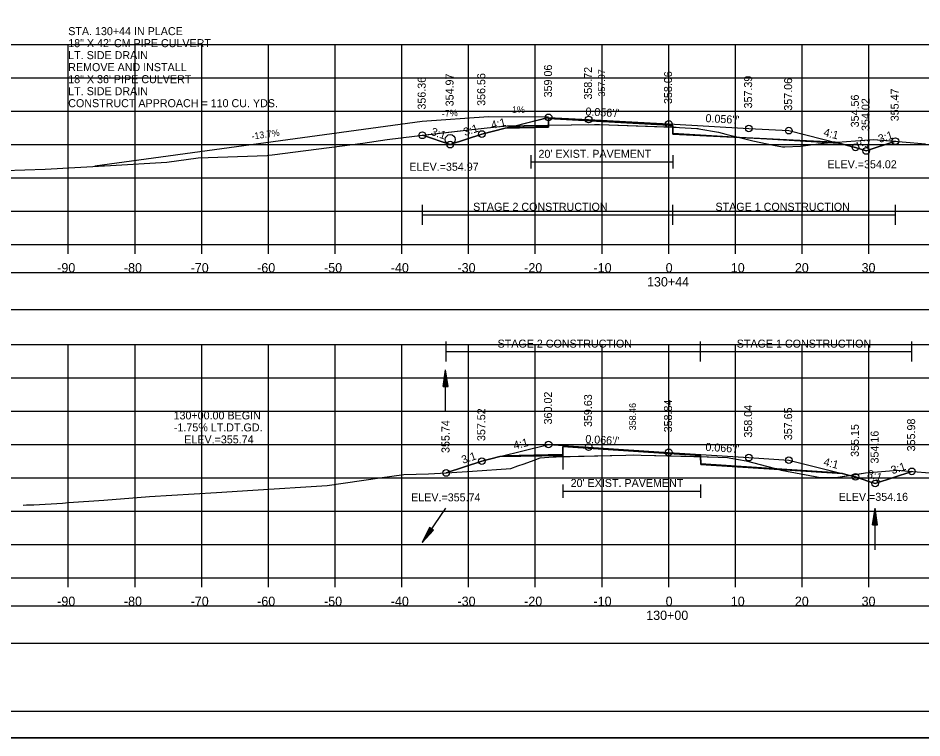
# Model space of a CAD drawing. Extents: x 1376273 to 1384221, y 378927 to 384592.
# Drawn here: x 1376960.2 to 1377095.7, y 381178.5 to 381286.4 of the extents above; entities that cross this region are included whole.
import ezdxf

# ---------------------------------------------------------------- set-up
doc = ezdxf.new("R2010")
doc.units = 0
for name, color, linetype in [('R_Alt Surface', 7, 'Continuous'), ('R_Axis', 7, 'Continuous'), ('R_Axis Annot', 7, 'Continuous'), ('R_Border', 7, 'Continuous'), ('R_Border Notes', 7, 'Continuous'), ('R_Dimension', 7, 'Continuous'), ('R_Drive', 7, 'Continuous'), ('R_Exist Surface', 7, 'Continuous'), ('R_Fin Surface', 7, 'Continuous'), ('R_Grid', 7, 'Continuous'), ('R_No Plot', 7, 'Continuous'), ('R_Water', 7, 'Continuous'), ('R_Xsect Elev', 7, 'Continuous'), ('R_Xsect Slope', 7, 'Continuous'), ('T_Detection Zones', 7, 'Continuous'), ('T_Notes', 7, 'Continuous'), ('T_Vehicle Path Lt Minor', 7, 'Continuous')]:
    doc.layers.add(name, color=color, linetype=linetype)

msp = doc.modelspace()

# ---------------------------------------------------------------- linework, layer by layer
at = {"layer": 'R_Alt Surface'}
for points in [[(1377033.97, 381270.11), (1377039.76, 381270.23), (1377039.77, 381271.4), (1377057.77, 381270.4), (1377058.37, 381270.36), (1377058.38, 381269.2), (1377083.26, 381267.69)], [(1377037.1, 381265.89), (1377037.1, 381263.89)], [(1377058.37, 381265.89), (1377058.37, 381263.89)], [(1377037.1, 381264.89), (1377058.37, 381264.89)], [(1377033.16, 381220.88), (1377041.91, 381221.06), (1377041.92, 381222.22), (1377057.77, 381221.18), (1377062.55, 381220.86), (1377062.56, 381219.69), (1377083.08, 381218.33)], [(1377041.92, 381216.54), (1377041.92, 381214.54)], [(1377041.92, 381215.54), (1377062.55, 381215.54)], [(1377062.55, 381216.54), (1377062.55, 381214.54)]]:
    msp.add_lwpolyline(points, dxfattribs=at)
at = {"layer": 'R_Axis'}
for p, q in [((1376907.77, 381252.51), (1377207.77, 381252.51)), ((1376967.77, 381251.11), (1376967.77, 381252.51)), ((1376977.77, 381251.11), (1376977.77, 381252.51)), ((1376987.77, 381251.11), (1376987.77, 381252.51)), ((1376997.77, 381251.11), (1376997.77, 381252.51)), ((1377007.77, 381251.11), (1377007.77, 381252.51)), ((1377017.77, 381251.11), (1377017.77, 381252.51)), ((1377027.77, 381251.11), (1377027.77, 381252.51)), ((1377037.77, 381251.11), (1377037.77, 381252.51)), ((1377047.77, 381251.11), (1377047.77, 381252.51)), ((1377057.77, 381251.11), (1377057.77, 381252.51)), ((1377067.77, 381251.11), (1377067.77, 381252.51)), ((1377077.77, 381251.11), (1377077.77, 381252.51)), ((1377087.77, 381251.11), (1377087.77, 381252.51)), ((1376907.77, 381202.51), (1377207.77, 381202.51)), ((1376967.77, 381201.11), (1376967.77, 381202.51)), ((1376977.77, 381201.11), (1376977.77, 381202.51)), ((1376987.77, 381201.11), (1376987.77, 381202.51)), ((1376997.77, 381201.11), (1376997.77, 381202.51)), ((1377007.77, 381201.11), (1377007.77, 381202.51)), ((1377017.77, 381201.11), (1377017.77, 381202.51)), ((1377027.77, 381201.11), (1377027.77, 381202.51)), ((1377037.77, 381201.11), (1377037.77, 381202.51)), ((1377047.77, 381201.11), (1377047.77, 381202.51)), ((1377057.77, 381201.11), (1377057.77, 381202.51)), ((1377067.77, 381201.11), (1377067.77, 381202.51)), ((1377077.77, 381201.11), (1377077.77, 381202.51)), ((1377087.77, 381201.11), (1377087.77, 381202.51))]:
    msp.add_line(p, q, dxfattribs=at)
at = {"layer": 'R_Axis Annot'}
for points in [[(1376907.2, 381242.74), (1377209.01, 381242.74), (1377209.01, 381248.26), (1376907.2, 381248.26)], [(1376907.2, 381192.74), (1377209.01, 381192.74), (1377209.01, 381198.26), (1376907.2, 381198.26)]]:
    msp.add_lwpolyline(points, close=True, dxfattribs=at)
at = {"layer": 'R_Border'}
msp.add_line((1377215.95, 381182.51), (1376899.77, 381182.51), dxfattribs=at)
at = {"layer": 'R_Dimension'}
for p, q in [((1377020.84, 381255.46), (1377020.84, 381258.46)), ((1377058.37, 381255.46), (1377058.37, 381258.46)), ((1377091.74, 381255.46), (1377091.74, 381258.46)), ((1377020.84, 381256.96), (1377091.74, 381256.96)), ((1377024.41, 381234.94), (1377024.41, 381237.94)), ((1377062.55, 381234.94), (1377062.55, 381237.94)), ((1377094.21, 381234.94), (1377094.21, 381237.94)), ((1377024.41, 381236.44), (1377094.21, 381236.44))]:
    msp.add_line(p, q, dxfattribs=at)
at = {"layer": 'R_Drive'}
for p, q in [((1377020.79, 381270.95), (1376971.77, 381264.23)), ((1377030.77, 381271.65), (1377020.79, 381270.95)), ((1377039.77, 381271.57), (1377030.77, 381271.65))]:
    msp.add_line(p, q, dxfattribs=at)
at = {"layer": 'R_Exist Surface'}
for points in [[(1376958.21, 381263.6), (1376964.31, 381263.82), (1376974.12, 381264.35), (1376982.56, 381264.83), (1376987.26, 381265.49), (1376997.57, 381265.86), (1376997.82, 381265.88), (1376998.31, 381265.95), (1377011.94, 381267.7), (1377015.58, 381268.25), (1377019.67, 381268.74), (1377028.25, 381269.75), (1377031.49, 381270.08), (1377033.56, 381270.28), (1377033.75, 381270.28), (1377035.49, 381270.31), (1377036.1, 381270.32), (1377046.66, 381270.47), (1377047.4, 381270.48), (1377058.88, 381270.07), (1377059.37, 381270.05), (1377061.96, 381269.88), (1377062.11, 381269.87), (1377062.29, 381269.84), (1377065.23, 381269.34), (1377066.33, 381269.06), (1377070.39, 381268.03), (1377073.47, 381267.42), (1377074.84, 381267.15), (1377075.19, 381267.16), (1377077.51, 381267.24), (1377080.57, 381267.63), (1377082.07, 381267.81), (1377083.05, 381267.87), (1377088.46, 381268.26), (1377093.94, 381267.79), (1377096.25, 381267.59)], [(1376960.99, 381213.43), (1376961.51, 381213.46), (1376962.61, 381213.45), (1376966.88, 381213.73), (1376967.82, 381213.82), (1376973.1, 381214.18), (1376979.95, 381214.72), (1376989.99, 381215.34), (1376995.45, 381215.65), (1377006.57, 381216.37), (1377014.48, 381217.51), (1377018.09, 381218.01), (1377021.76, 381218.13), (1377024.48, 381218.25), (1377028.35, 381218.54), (1377034.1, 381218.93), (1377035.13, 381219.3), (1377036.12, 381219.64), (1377037.62, 381220.18), (1377038.5, 381220.53), (1377040.47, 381220.66), (1377040.92, 381220.69), (1377051.36, 381220.94), (1377052.55, 381220.97), (1377053.65, 381220.93), (1377063.55, 381220.67), (1377063.72, 381220.66), (1377066.58, 381220.58), (1377067.06, 381220.49), (1377069.38, 381220.07), (1377073.56, 381218.96), (1377074.61, 381218.68), (1377079.71, 381217.72), (1377080.47, 381217.57), (1377082.71, 381217.56), (1377082.74, 381217.56), (1377082.84, 381217.57), (1377087.28, 381218.26), (1377087.89, 381218.32), (1377092.08, 381218.66), (1377094.34, 381218.48), (1377099.46, 381218.06)]]:
    msp.add_lwpolyline(points, dxfattribs=at)
at = {"layer": 'R_Fin Surface'}
for points in [[(1377020.84, 381268.87), (1377025.02, 381267.48), (1377029.77, 381269.06), (1377033.26, 381269.94), (1377039.77, 381271.56), (1377045.77, 381271.23), (1377057.77, 381270.57), (1377069.77, 381269.9), (1377075.77, 381269.57), (1377085.77, 381267.07), (1377087.38, 381266.53), (1377091.74, 381267.98)], [(1377024.41, 381218.25), (1377024.42, 381218.25), (1377029.77, 381220.03), (1377032.45, 381220.7), (1377039.77, 381222.53), (1377045.77, 381222.14), (1377057.77, 381221.34), (1377069.77, 381220.55), (1377075.77, 381220.16), (1377085.77, 381217.66), (1377087.75, 381216.99), (1377088.73, 381216.67), (1377094.21, 381218.49)]]:
    msp.add_lwpolyline(points, dxfattribs=at)
at = {"layer": 'R_Grid'}
for p, q in [((1376907.77, 381282.51), (1377207.77, 381282.51)), ((1376907.77, 381282.51), (1377207.77, 381282.51)), ((1376967.77, 381252.51), (1376967.77, 381282.51)), ((1376967.77, 381252.51), (1376967.77, 381282.51)), ((1376977.77, 381252.51), (1376977.77, 381282.51)), ((1376977.77, 381252.51), (1376977.77, 381282.51)), ((1376987.77, 381252.51), (1376987.77, 381282.51)), ((1376987.77, 381252.51), (1376987.77, 381282.51)), ((1376997.77, 381252.51), (1376997.77, 381282.51)), ((1376997.77, 381252.51), (1376997.77, 381282.51)), ((1377007.77, 381252.51), (1377007.77, 381282.51)), ((1377007.77, 381252.51), (1377007.77, 381282.51)), ((1377017.77, 381252.51), (1377017.77, 381282.51)), ((1377017.77, 381252.51), (1377017.77, 381282.51)), ((1377027.77, 381252.51), (1377027.77, 381282.51)), ((1377027.77, 381252.51), (1377027.77, 381282.51)), ((1377037.77, 381252.51), (1377037.77, 381282.51)), ((1377037.77, 381252.51), (1377037.77, 381282.51)), ((1377047.77, 381252.51), (1377047.77, 381282.51)), ((1377047.77, 381252.51), (1377047.77, 381282.51)), ((1377057.77, 381252.51), (1377057.77, 381282.51)), ((1377057.77, 381252.51), (1377057.77, 381282.51)), ((1377067.77, 381252.51), (1377067.77, 381282.51)), ((1377067.77, 381252.51), (1377067.77, 381282.51)), ((1377077.77, 381252.51), (1377077.77, 381282.51)), ((1377077.77, 381252.51), (1377077.77, 381282.51)), ((1377087.77, 381252.51), (1377087.77, 381282.51)), ((1377087.77, 381252.51), (1377087.77, 381282.51)), ((1376907.77, 381277.51), (1377207.77, 381277.51)), ((1376907.77, 381277.51), (1377207.77, 381277.51)), ((1376907.77, 381272.51), (1377207.77, 381272.51)), ((1376907.77, 381272.51), (1377207.77, 381272.51)), ((1376907.77, 381267.51), (1377207.77, 381267.51)), ((1376907.77, 381267.51), (1377207.77, 381267.51)), ((1376907.77, 381262.51), (1377207.77, 381262.51)), ((1376907.77, 381262.51), (1377207.77, 381262.51)), ((1376907.77, 381257.51), (1377207.77, 381257.51)), ((1376907.77, 381257.51), (1377207.77, 381257.51)), ((1376907.77, 381252.51), (1377207.77, 381252.51)), ((1376907.77, 381252.51), (1377207.77, 381252.51)), ((1376907.77, 381237.51), (1377207.77, 381237.51)), ((1376907.77, 381237.51), (1377207.77, 381237.51)), ((1376967.77, 381202.51), (1376967.77, 381237.51)), ((1376967.77, 381202.51), (1376967.77, 381237.51)), ((1376977.77, 381202.51), (1376977.77, 381237.51)), ((1376977.77, 381202.51), (1376977.77, 381237.51)), ((1376987.77, 381202.51), (1376987.77, 381237.51)), ((1376987.77, 381202.51), (1376987.77, 381237.51)), ((1376997.77, 381202.51), (1376997.77, 381237.51)), ((1376997.77, 381202.51), (1376997.77, 381237.51)), ((1377007.77, 381202.51), (1377007.77, 381237.51)), ((1377007.77, 381202.51), (1377007.77, 381237.51)), ((1377017.77, 381202.51), (1377017.77, 381237.51)), ((1377017.77, 381202.51), (1377017.77, 381237.51)), ((1377027.77, 381202.51), (1377027.77, 381237.51)), ((1377027.77, 381202.51), (1377027.77, 381237.51)), ((1377037.77, 381202.51), (1377037.77, 381237.51)), ((1377037.77, 381202.51), (1377037.77, 381237.51)), ((1377047.77, 381202.51), (1377047.77, 381237.51)), ((1377047.77, 381202.51), (1377047.77, 381237.51)), ((1377057.77, 381202.51), (1377057.77, 381237.51)), ((1377057.77, 381202.51), (1377057.77, 381237.51)), ((1377067.77, 381202.51), (1377067.77, 381237.51)), ((1377067.77, 381202.51), (1377067.77, 381237.51)), ((1377077.77, 381202.51), (1377077.77, 381237.51)), ((1377077.77, 381202.51), (1377077.77, 381237.51)), ((1377087.77, 381202.51), (1377087.77, 381237.51)), ((1377087.77, 381202.51), (1377087.77, 381237.51)), ((1376907.77, 381232.51), (1377207.77, 381232.51)), ((1376907.77, 381232.51), (1377207.77, 381232.51)), ((1376907.77, 381227.51), (1377207.77, 381227.51)), ((1376907.77, 381227.51), (1377207.77, 381227.51)), ((1376907.77, 381222.51), (1377207.77, 381222.51)), ((1376907.77, 381222.51), (1377207.77, 381222.51)), ((1376907.77, 381217.51), (1377207.77, 381217.51)), ((1376907.77, 381217.51), (1377207.77, 381217.51)), ((1376907.77, 381212.51), (1377207.77, 381212.51)), ((1376907.77, 381212.51), (1377207.77, 381212.51)), ((1376907.77, 381207.51), (1377207.77, 381207.51)), ((1376907.77, 381207.51), (1377207.77, 381207.51)), ((1376907.77, 381202.51), (1377207.77, 381202.51)), ((1376907.77, 381202.51), (1377207.77, 381202.51))]:
    msp.add_line(p, q, dxfattribs=at)
at = {"layer": 'R_No Plot'}
msp.add_line((1376887.37, 381178.53), (1377220.7, 381178.53), dxfattribs=at)
for points in [[(1376887.36, 381391.86), (1377220.7, 381391.86), (1377220.7, 381178.53), (1376887.36, 381178.53)], [(1377133.69, 381387.97), (1377133.69, 381378.09), (1377169.42, 381378.09), (1377169.42, 381375.17), (1377192.62, 381375.17), (1377192.62, 381350.84), (1377215.95, 381350.84), (1377215.95, 381182.51), (1376899.77, 381182.51), (1376899.77, 381387.97)]]:
    msp.add_lwpolyline(points, close=True, dxfattribs=at)
for points in [[(1377033.26, 381269.94), (1377039.76, 381270.07), (1377039.77, 381271.4), (1377057.77, 381270.4), (1377058.37, 381270.36), (1377058.38, 381269.03), (1377082.72, 381267.83)], [(1377032.45, 381220.7), (1377041.91, 381220.89), (1377041.92, 381222.22), (1377057.77, 381221.18), (1377062.55, 381220.86), (1377062.56, 381219.53), (1377083.81, 381218.15)]]:
    msp.add_lwpolyline(points, dxfattribs=at)
for centre in [(1377039.77, 381271.56), (1377039.77, 381271.56), (1377045.77, 381271.23), (1377045.77, 381271.23), (1377057.77, 381270.57), (1377057.77, 381270.57), (1377029.77, 381269.06), (1377029.77, 381269.06), (1377069.77, 381269.9), (1377069.77, 381269.9), (1377075.77, 381269.57), (1377075.77, 381269.57), (1377020.84, 381268.87), (1377020.84, 381268.87), (1377091.74, 381267.98), (1377091.74, 381267.98), (1377025.02, 381267.48), (1377025.02, 381267.48), (1377025.02, 381267.48), (1377025.02, 381267.48), (1377085.77, 381267.07), (1377085.77, 381267.07), (1377087.38, 381266.53), (1377087.38, 381266.53), (1377087.38, 381266.53), (1377087.38, 381266.53), (1377039.77, 381222.53), (1377039.77, 381222.53), (1377045.77, 381222.14), (1377045.77, 381222.14), (1377057.77, 381221.34), (1377057.77, 381221.34), (1377069.77, 381220.55), (1377069.77, 381220.55), (1377029.77, 381220.03), (1377029.77, 381220.03), (1377075.77, 381220.16), (1377075.77, 381220.16), (1377024.41, 381218.25), (1377024.41, 381218.25), (1377024.42, 381218.25), (1377024.42, 381218.25), (1377024.42, 381218.25), (1377024.42, 381218.25), (1377085.77, 381217.66), (1377085.77, 381217.66), (1377094.21, 381218.49), (1377094.21, 381218.49), (1377088.73, 381216.67), (1377088.73, 381216.67), (1377088.73, 381216.67), (1377088.73, 381216.67)]:
    msp.add_circle(centre, 0.5, dxfattribs=at)
at = {"layer": 'R_Water'}
for p, q in [((1377023.94, 381231.21), (1377024.32, 381233.71)), ((1377024, 381231.21), (1377024.32, 381233.29)), ((1377024.32, 381227.46), (1377024.32, 381233.71)), ((1377024.69, 381231.21), (1377024.32, 381233.71)), ((1377024.63, 381231.21), (1377024.32, 381233.29)), ((1377024.07, 381231.21), (1377024.32, 381232.86)), ((1377024.13, 381231.21), (1377024.32, 381232.45)), ((1377024.2, 381231.21), (1377024.32, 381232.02)), ((1377024.57, 381231.21), (1377024.32, 381232.86)), ((1377024.5, 381231.21), (1377024.32, 381232.45)), ((1377024.44, 381231.21), (1377024.32, 381232.02)), ((1377023.94, 381231.21), (1377024.69, 381231.21)), ((1377024.26, 381231.21), (1377024.32, 381231.61)), ((1377024.38, 381231.21), (1377024.32, 381231.61)), ((1377024.32, 381212.97), (1377020.81, 381207.8)), ((1377088.34, 381210.47), (1377088.72, 381212.97)), ((1377088.72, 381206.72), (1377088.72, 381212.97)), ((1377089.09, 381210.47), (1377088.72, 381212.97)), ((1377088.4, 381210.47), (1377088.72, 381212.55)), ((1377088.47, 381210.47), (1377088.72, 381212.12)), ((1377088.53, 381210.47), (1377088.72, 381211.71)), ((1377089.03, 381210.47), (1377088.72, 381212.55)), ((1377088.96, 381210.47), (1377088.72, 381212.12)), ((1377088.9, 381210.47), (1377088.72, 381211.71)), ((1377021.9, 381210.08), (1377020.81, 381207.8)), ((1377021.96, 381210.04), (1377021.05, 381208.14)), ((1377022.01, 381210.01), (1377021.29, 381208.5)), ((1377022.06, 381209.97), (1377021.52, 381208.84)), ((1377022.52, 381209.66), (1377021.9, 381210.08)), ((1377088.34, 381210.47), (1377089.09, 381210.47)), ((1377088.59, 381210.47), (1377088.72, 381211.28)), ((1377088.66, 381210.47), (1377088.72, 381210.87)), ((1377088.84, 381210.47), (1377088.72, 381211.28)), ((1377088.77, 381210.47), (1377088.72, 381210.87)), ((1377022.52, 381209.66), (1377020.81, 381207.8)), ((1377022.47, 381209.69), (1377021.05, 381208.14)), ((1377022.42, 381209.73), (1377021.29, 381208.5)), ((1377022.37, 381209.76), (1377021.52, 381208.84)), ((1377022.11, 381209.94), (1377021.76, 381209.19)), ((1377022.31, 381209.8), (1377021.76, 381209.19)), ((1377022.17, 381209.9), (1377021.99, 381209.54)), ((1377022.26, 381209.83), (1377021.99, 381209.54))]:
    msp.add_line(p, q, dxfattribs=at)
msp.add_circle((1377025.02, 381268.23), 0.75, dxfattribs=at)
at = {"layer": 'T_Detection Zones'}
for p, q in [((1377041.91, 381220.89), (1377032.45, 381220.7)), ((1377041.91, 381220.89), (1377041.91, 381218.79)), ((1377041.91, 381220.71), (1377041.91, 381220.89))]:
    msp.add_line(p, q, dxfattribs=at)
for points in [[(1377020.84, 381268.87), (1377028.25, 381269.75), (1377031.49, 381270.08), (1377033.56, 381270.28), (1377033.75, 381270.28), (1377035.49, 381270.31), (1377036.1, 381270.32), (1377039.76, 381270.37), (1377039.76, 381270.07), (1377033.26, 381269.94), (1377029.77, 381269.06), (1377025.02, 381267.48)], [(1377058.37, 381270.08), (1377058.88, 381270.07), (1377059.37, 381270.05), (1377061.96, 381269.88), (1377062.11, 381269.87), (1377062.29, 381269.84), (1377065.23, 381269.34), (1377066.33, 381269.06), (1377068.4, 381268.54), (1377058.38, 381269.03)], [(1377068.4, 381268.54), (1377070.39, 381268.03), (1377073.47, 381267.42), (1377074.84, 381267.15), (1377075.19, 381267.16), (1377077.51, 381267.24), (1377080.57, 381267.63), (1377082.07, 381267.81), (1377082.49, 381267.84)], [(1377082.49, 381267.84), (1377083.05, 381267.87), (1377088.46, 381268.26), (1377091.74, 381267.98), (1377087.38, 381266.53), (1377085.77, 381267.07), (1377082.72, 381267.83)], [(1377062.55, 381220.7), (1377063.55, 381220.67), (1377063.72, 381220.66), (1377066.58, 381220.58), (1377067.06, 381220.49), (1377069.38, 381220.07), (1377073.56, 381218.96), (1377074.3, 381218.77), (1377062.56, 381219.53)], [(1377074.3, 381218.77), (1377074.61, 381218.68), (1377079.71, 381217.72), (1377080.47, 381217.57), (1377082.71, 381217.56), (1377082.74, 381217.56), (1377082.84, 381217.57), (1377084.86, 381217.88), (1377083.81, 381218.15)], [(1377084.86, 381217.88), (1377087.28, 381218.26), (1377087.89, 381218.32), (1377092.08, 381218.66), (1377094.21, 381218.49), (1377088.73, 381216.67), (1377087.75, 381216.99), (1377085.77, 381217.66)]]:
    msp.add_lwpolyline(points, close=True, dxfattribs=at)
for points in [[(1377024.41, 381218.25), (1377024.48, 381218.25), (1377028.35, 381218.54), (1377034.1, 381218.93), (1377035.13, 381219.3), (1377036.12, 381219.64), (1377037.62, 381220.18), (1377038.5, 381220.53), (1377040.47, 381220.66), (1377040.92, 381220.69), (1377041.91, 381220.71)], [(1377032.45, 381220.7), (1377029.77, 381220.03), (1377024.41, 381218.25)]]:
    msp.add_lwpolyline(points, dxfattribs=at)
at = {"layer": 'T_Notes'}
for p, q in [((1377020.79, 381270.95), (1376971.77, 381264.23)), ((1377030.77, 381271.65), (1377020.79, 381270.95)), ((1377039.77, 381271.57), (1377030.77, 381271.65))]:
    msp.add_line(p, q, dxfattribs=at)
for points in [[(1377020.84, 381268.87), (1377025.02, 381267.48), (1377029.77, 381269.06), (1377034, 381270.12), (1377034.7, 381270.3), (1377039.77, 381271.57)], [(1376971.77, 381264.23), (1376974.12, 381264.35), (1376982.56, 381264.83), (1376987.26, 381265.49), (1376997.57, 381265.86), (1376997.82, 381265.88), (1376998.31, 381265.95), (1377011.94, 381267.7), (1377015.58, 381268.25), (1377019.67, 381268.74), (1377020.84, 381268.87)]]:
    msp.add_lwpolyline(points, dxfattribs=at)
at = {"layer": 'T_Vehicle Path Lt Minor'}
for p, q in [((1377041.91, 381220.89), (1377041.91, 381220.71)), ((1377062.55, 381220.7), (1377062.55, 381220.86))]:
    msp.add_line(p, q, dxfattribs=at)
msp.add_lwpolyline([(1377039.76, 381270.37), (1377046.66, 381270.47), (1377047.4, 381270.48), (1377058.37, 381270.08), (1377058.37, 381270.36), (1377057.77, 381270.4), (1377039.77, 381271.4)], close=True, dxfattribs=at)
for points in [[(1377062.55, 381220.86), (1377057.77, 381221.18), (1377041.92, 381222.22), (1377041.91, 381220.89)], [(1377041.91, 381220.71), (1377051.36, 381220.94), (1377052.55, 381220.97), (1377053.65, 381220.93), (1377062.55, 381220.7)]]:
    msp.add_lwpolyline(points, dxfattribs=at)

# ---------------------------------------------------------------- texts
at = {"layer": 'R_Alt Surface'}
for p in [(1377038.25, 381265.5), (1377043.07, 381216.15)]:
    msp.add_text("20' EXIST. PAVEMENT", height=1.2, dxfattribs=at).set_placement(p)
at = {"layer": 'R_Axis Annot'}
for s, p in [('-90', (1376966.11, 381248.31)), ('-80', (1376976.11, 381248.31)), ('-70', (1376986.11, 381248.31)), ('-60', (1376996.08, 381248.31)), ('-50', (1377006.11, 381248.31)), ('-40', (1377016.11, 381248.31)), ('-30', (1377026.11, 381248.31)), ('-20', (1377036.11, 381248.31)), ('-10', (1377046.5, 381248.31)), ('0', (1377057.31, 381248.31)), ('10', (1377067.08, 381248.31)), ('20', (1377076.68, 381248.31)), ('30', (1377086.68, 381248.31)), ('130+44', (1377054.52, 381246.21)), ('-90', (1376966.11, 381198.31)), ('-80', (1376976.11, 381198.31)), ('-70', (1376986.11, 381198.31)), ('-60', (1376996.08, 381198.31)), ('-50', (1377006.11, 381198.31)), ('-40', (1377016.11, 381198.31)), ('-30', (1377026.11, 381198.31)), ('-20', (1377036.11, 381198.31)), ('-10', (1377046.5, 381198.31)), ('0', (1377057.31, 381198.31)), ('10', (1377067.08, 381198.31)), ('20', (1377076.68, 381198.31)), ('30', (1377086.68, 381198.31)), ('130+00', (1377054.4, 381196.21))]:
    msp.add_text(s, height=1.4, dxfattribs=at).set_placement(p)
at = {"layer": 'R_Border Notes'}
for s, p in [('ELEV.=354.97', (1377018.89, 381263.56)), ('ELEV.=354.02', (1377081.56, 381263.93)), ('ELEV.=355.74', (1377019.16, 381213.99)), ('ELEV.=354.16', (1377083.25, 381214.07))]:
    msp.add_text(s, height=1.2, dxfattribs=at).set_placement(p)
at = {"layer": 'R_Dimension'}
for s, p in [('STAGE 2 CONSTRUCTION', (1377028.46, 381257.56)), ('STAGE 1 CONSTRUCTION', (1377064.78, 381257.56)), ('STAGE 2 CONSTRUCTION', (1377032.12, 381237.04)), ('STAGE 1 CONSTRUCTION', (1377067.97, 381237.04))]:
    msp.add_text(s, height=1.2, dxfattribs=at).set_placement(p)
at = {"layer": 'R_Drive'}
for s, p in [('STA. 130+44 IN PLACE', (1376967.76, 381283.89)), ('18" X 42\' CM PIPE CULVERT', (1376967.76, 381282.09)), ('LT. SIDE DRAIN', (1376967.76, 381280.29)), ('REMOVE AND INSTALL', (1376967.76, 381278.49)), ('18" X 36\' PIPE CULVERT', (1376967.76, 381276.69)), ('LT. SIDE DRAIN', (1376967.76, 381274.89)), ('CONSTRUCT APPROACH = 110 CU. YDS.', (1376967.76, 381273.09))]:
    msp.add_text(s, height=1.2, dxfattribs=at).set_placement(p)
for s, rotation, p in [('-7%', 4.0253, (1377023.79, 381271.6)), ('1%', 359.4513, (1377034.27, 381272.23)), ('-13.7%', 7.8114, (1376995.3, 381268.23))]:
    msp.add_text(s, height=1, rotation=rotation, dxfattribs=at).set_placement(p)
at = {"layer": 'R_Xsect Elev'}
for s, height, rotation, p in [('359.06', 1.2, 90, (1377040.27, 381274.56)), ('358.72', 1.2, 90, (1377046.27, 381274.23)), ('354.97', 1.2, 90, (1377025.52, 381273.22)), ('356.56', 1.2, 90, (1377030.27, 381273.29)), ('357.97', 1, 90, (1377048.22, 381274.68)), ('358.06', 1.2, 90, (1377058.27, 381273.57)), ('357.39', 1.2, 90, (1377070.27, 381272.9)), ('356.36', 1.2, 90, (1377021.34, 381272.73)), ('357.06', 1.2, 90, (1377076.27, 381272.57)), ('355.47', 1.2, 90, (1377092.24, 381270.98)), ('354.56', 1.2, 90, (1377086.27, 381270.07)), ('354.02', 1.2, 90, (1377087.88, 381269.53)), ('360.02', 1.2, 90, (1377040.27, 381225.53)), ('359.63', 1.2, 90, (1377046.27, 381225.14)), ('358.84', 1.2, 90, (1377058.27, 381224.34)), ('357.52', 1.2, 90, (1377030.27, 381223.03)), ('358.46', 1, 90, (1377052.85, 381224.65)), ('358.04', 1.2, 90, (1377070.27, 381223.55)), ('357.65', 1.2, 90, (1377076.27, 381223.16)), ('130+00.00 BEGIN', 1.2, 360, (1376983.55, 381226.28)), ('355.98', 1.2, 90, (1377094.71, 381221.49)), ('-1.75% LT.DT.GD.', 1.2, 360, (1376983.6, 381224.48)), ('355.74', 1.2, 90, (1377024.91, 381221.25)), ('355.74', 1.2, 90, (1377024.92, 381221.25)), ('355.15', 1.2, 90, (1377086.27, 381220.66)), ('ELEV.=355.74', 1.2, 360, (1376985.15, 381222.68)), ('354.16', 1.2, 90, (1377089.23, 381219.67))]:
    msp.add_text(s, height=height, rotation=rotation, dxfattribs=at).set_placement(p)
at = {"layer": 'R_Xsect Slope'}
for s, rotation, p in [("0.056'/'", 356.8227, (1377045.26, 381271.86)), ('4:1', 14.0362, (1377031.29, 381269.8)), ("0.056'/'", 356.8227, (1377063.26, 381270.86)), ('3:1', 341.5651, (1377022.03, 381268.94)), ('3:1', 18.4349, (1377027.23, 381268.75)), ('4:1', 345.9638, (1377080.89, 381268.8)), ('3:1', 341.5651, (1377085.77, 381267.61)), ('3:1', 18.4349, (1377089.4, 381267.73)), ("0.066'/'", 356.2244, (1377045.24, 381222.77)), ('4:1', 14.0362, (1377034.65, 381221.77)), ("0.066'/'", 356.2244, (1377063.24, 381221.58)), ('3:1', 18.4349, (1377026.93, 381219.61)), ('4:1', 345.9638, (1377080.89, 381219.39)), ('3:1', 18.4349, (1377091.31, 381218.05)), ('3:1', 341.5651, (1377087.41, 381217.64))]:
    msp.add_text(s, height=1.2, rotation=rotation, dxfattribs=at).set_placement(p)

doc.saveas('drawing.dxf')
